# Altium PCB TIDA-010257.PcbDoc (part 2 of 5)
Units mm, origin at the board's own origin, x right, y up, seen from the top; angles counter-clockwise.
Board outline 250 x 270 mm, 2 copper layers (Top Layer, Bottom Layer), stack 1.575 mm thick; 458 components, 220 nets, 1154 pads, 1226 vias.
Unrouted connection lines stored in the file: 314.
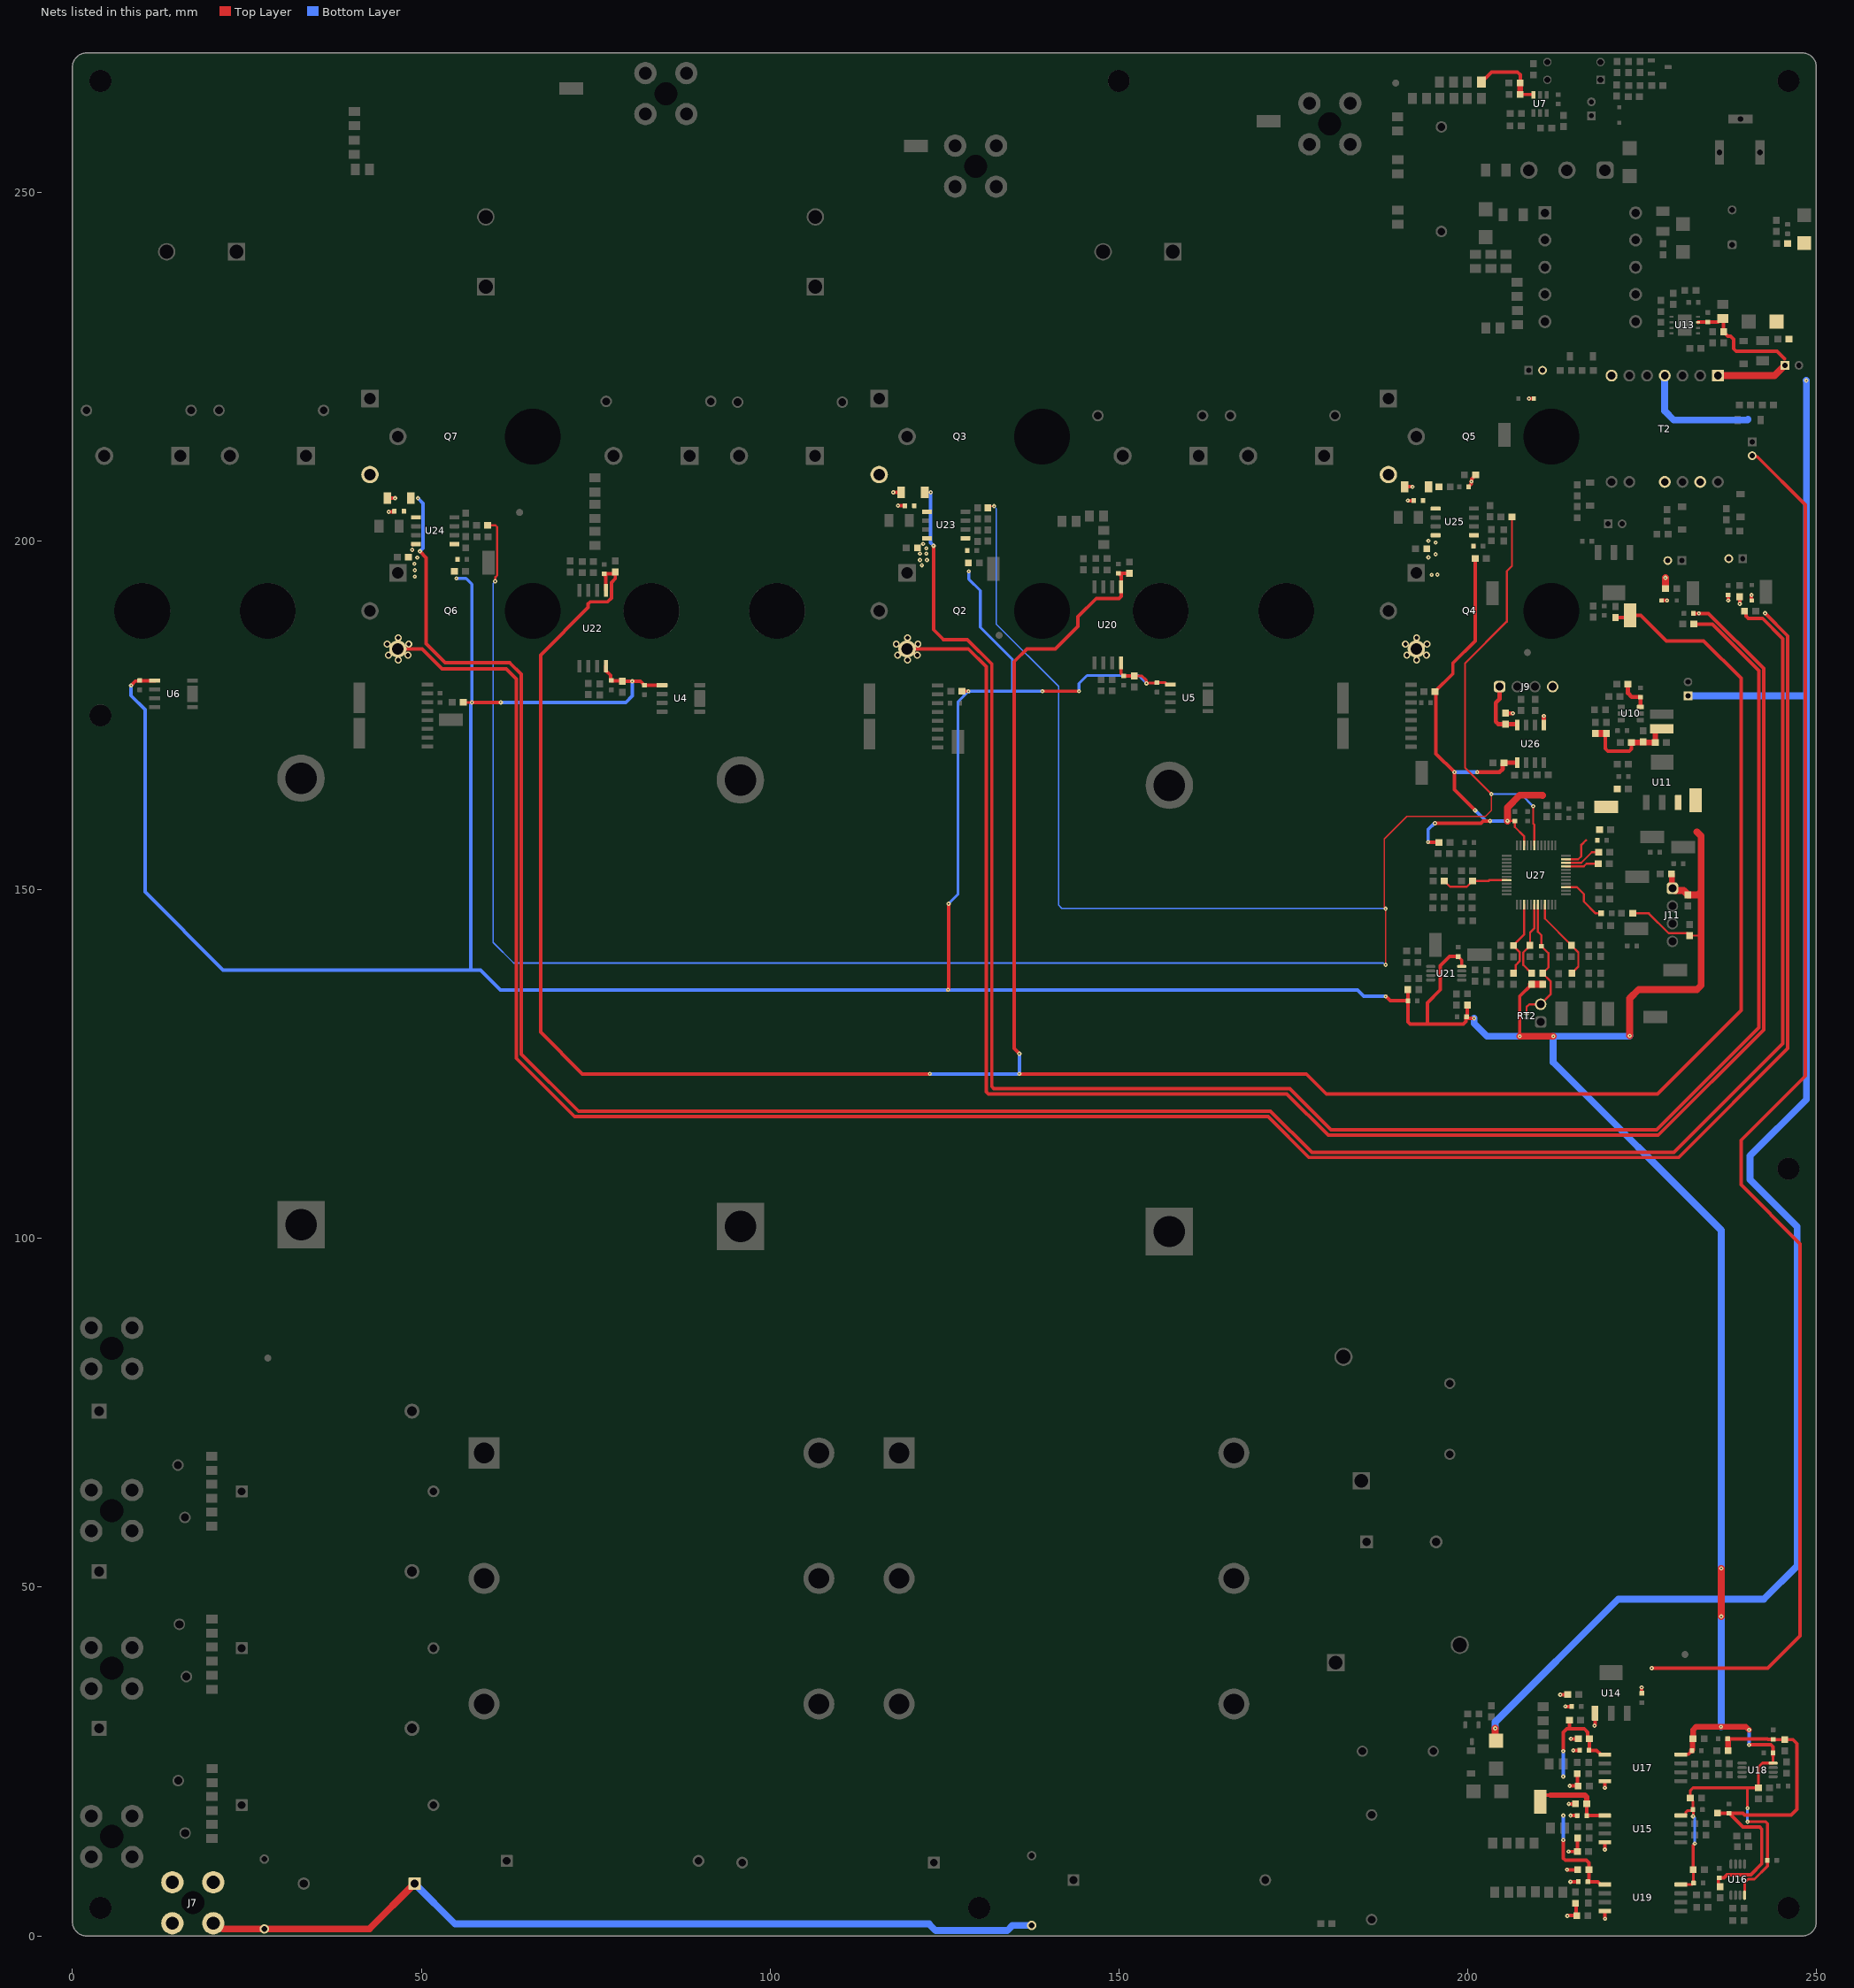
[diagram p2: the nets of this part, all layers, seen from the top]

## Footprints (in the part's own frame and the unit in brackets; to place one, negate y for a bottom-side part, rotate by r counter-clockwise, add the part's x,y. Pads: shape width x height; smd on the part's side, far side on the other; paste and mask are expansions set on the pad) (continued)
NGU0008C [mm] "SON, 8-Leads, Body 4x4mm, Pitch 0.8mm"
  rrect33% 0.6x0.3 smd: 1(-1.9,1.2) 2(-1.9,0.4) 3(-1.9,-0.4) 4(-1.9,-1.2) 5(1.9,-1.2) 6(1.9,-0.4) 7(1.9,0.4) 8(1.9,1.2)
  rrect8% 1.75x1.31 on Top Paste: 9(0,0.755) 9(0,-0.755)
  rrect5% 1.98x3 smd paste-1.5: 9(0,0)
  silkscreen extent -2.15,-2.15 2.15,2.15, body extent -2,-2 2,2, height 0.77
PT0048A-MFG [mm]
  rrect33% 1.4x0.3 smd paste-1000 mask+0: 1(-4.25,2.75) 2(-4.25,2.25) 3(-4.25,1.75) 4(-4.25,1.25) 5(-4.25,0.75) 6(-4.25,0.25) 7(-4.25,-0.25) 8(-4.25,-0.75) 9(-4.25,-1.25) 10(-4.25,-1.75) 11(-4.25,-2.25) 12(-4.25,-2.75) 25(4.25,-2.75) 26(4.25,-2.25) 27(4.25,-1.75) 28(4.25,-1.25) 29(4.25,-0.75) 30(4.25,-0.25) 31(4.25,0.25) 32(4.25,0.75) 33(4.25,1.25) 34(4.25,1.75) 35(4.25,2.25) 36(4.25,2.75)
  rrect33% 0.3x1.4 smd paste-1000 mask+0: 13(-2.75,-4.25) 14(-2.25,-4.25) 15(-1.75,-4.25) 16(-1.25,-4.25) 17(-0.75,-4.25) 18(-0.25,-4.25) 19(0.25,-4.25) 20(0.75,-4.25) 21(1.25,-4.25) 22(1.75,-4.25) 23(2.25,-4.25) 24(2.75,-4.25) 37(2.75,4.25) 38(2.25,4.25) 39(1.75,4.25) 40(1.25,4.25) 41(0.75,4.25) 42(0.25,4.25) 43(-0.25,4.25) 44(-0.75,4.25) 45(-1.25,4.25) 46(-1.75,4.25) 47(-2.25,4.25) 48(-2.75,4.25)
  silkscreen extent -5.65,-3.6 3.6,3.6, body extent -5.05,-5.05 5.05,5.05, height 0.25
PW_500x700 [mm] "Nichicon"
  rect 1.25x1.25 hole 0.711: 1(-1,0)
  round 1.25 hole 0.711: 2(1,0)
  silkscreen extent -2.8,-2.8 2.8,2.8, body extent -2.73,-2.75 2.75,2.75, height 8.01
Relay_T9AS1D12 [mm] "TH, 4-Leads, Body 32.51x27.43mm"
  rect 2.5x2.5 hole 1.98: 1(-8.89,5.08)
  round 2.6 hole 2.06: 2(8.89,7.62)
  round 1.6 hole 1.09: 3(-5.08,-7.62) 4(5.08,-7.62)
  silkscreen extent -13.79,-14.73 14.15,17.79, body extent -13.26,-14.73 14.17,17.78, height 20.45
SMA [mm] "Molded Diode, 2-Leads, Body 4.3x2.6mm, IPC Medium Density, based on OnSemi component dimensions and land pattern"
  rect 2x2 smd: 1(-2,0) 2(2,0)
  silkscreen extent -3.66,-1.57 2.79,1.57, body extent -2.6,-1.3 2.6,1.3, height 2.42
SOD-123 [mm] "On Semi recommended land pattern"
  rect 0.915x1.22 smd: 1(-1.637,0) 2(1.637,0)
  silkscreen extent -2.74,-1.17 2.03,1.17, body extent -1.93,-0.9 1.93,0.9, height 1.35
SOD-123FL [mm] "Copied from SOD-123"
  rect 0.915x1.22 smd: 1(-1.637,0) 2(1.637,0)
  silkscreen extent -2.74,-1.16 1.68,1.16, body extent -1.9,-0.9 1.9,0.9, height 1
SOD-323 [mm] "NXP recommended land pattern"
  rect 0.6x0.6 smd paste-0.05: 1(-1.1,0) 2(1.1,0)
  silkscreen extent -2.06,-0.86 1.53,0.86, body extent -1.3,-0.67 1.3,0.68, height 1.1
SOT-23 [mm] "SOT23, 3-Leads, Body 2.9x1.3mm, Pitch 0.95mm, Lead Span 2.5mm, IPC Medium Density"
  rrect50% 1x0.6 smd: 1(-1.2,0.95) 2(-1.2,-0.95) 3(1.2,0)
  silkscreen extent -1.63,-1.5 0.7,1.5, body extent -1.16,-1.45 1.21,1.45, height 1
Testpoint_Keystone_Miniature [mil] "Miniature SMT test point"
  rect 135x70 smd: 1(0,0)
  silkscreen extent -78,-46 78,45, body extent -52,-20 52,20, height 61
TI_Stacked_Overlay_Small [mm]
  silkscreen extent -10.63,-2.49 10.63,2.49
TO-3P [mm] "IXYS"
  rrect50% 2.5x2.5 hole 1.65: 1(-5.45,0)
  round 2.5 hole 1.65: 2(0,0) 3(5.45,0)
  body extent -7.8,-3.05 7.8,1.66, height 23.4
WCAP-FTBE_L18W8.5H15 [mm] "THT Film Capacitors, body 18x8.5mm"
  round 1.65 hole 1.1: 1(-7.5,0) 2(7.5,0)
  silkscreen extent -9.75,-4.75 9.75,4.75, body extent -9,-4.25 9,4.25, height 15.05
WCAP-FTXX_P15PL20_1800x600 [mm] "TH, 2-Leads, Body 18x6mm"
  round 1.65 hole 1.1: 1(-7.5,0) 2(7.5,0)
  silkscreen extent -9.25,-3.25 9.25,3.25, body extent -9.25,-3.25 9.25,3.25, height 12.5
WE-MAIA_3015 [mm] "SMD, 2-Leads, Body 3x3mm"
  rect 1.3x3.4 smd: 1(-1.05,0) 2(1.05,0)
  silkscreen extent -0.1,-1.6 0.1,1.6, body extent -1.6,-1.6 1.6,1.6, height 1.5
WEEE_Minimum [mm] "WEEElie bin"
  silkscreen extent -2.42,-4.38 2.52,2.65
WURTH_61300211121 [mm] "Header, 2.54mm, 2x1, TH"
  rrect50% 1.65x1.65 hole 1.15: 1(-1.27,0)
  round 1.65 hole 1.15: 2(1.27,0)
  body extent -2.54,-1.27 2.54,1.27, height 8.54
WURTH_61300411121 [mm] "Header, 2.54mm, 4x1, TH"
  rrect50% 1.65x1.65 hole 1.15: 1(-3.81,0)
  round 1.65 hole 1.15: 2(-1.27,0) 3(1.27,0) 4(3.81,0)
  body extent -5.08,-1.27 5.08,1.27, height 8.54
Wurth_694106301002 [mm] "WR-DC DC Power Jack, R/A, TH"
  rect 3.5x1.3 hole 0.8 slot 3 at 0 deg: 1(0,-2.9) 2(0,2.9)
  rect 1.3x3.5 hole 0.8 slot 3 at 90 deg: 3(-4.8,0.1)
  silkscreen extent -4.5,-3.8 4.9,10.7, body extent -4.9,-3.8 4.5,10.7, height 10.63
Wurth_WP-THRBU [mm] "Power Element Bush, M3, TH"
  round 3.2 hole 1.85: 1(-2.935,2.935) 1(-2.935,-2.935) 1(2.935,2.935) 1(2.935,-2.935)
  round 3.1 on Top Paste: ""(-2.935,2.935) ""(-2.935,-2.935) ""(2.935,2.935) ""(2.935,-2.935)
  round 3 hole 3.3 unplated mask+0.102: ""(0,0)
  silkscreen extent -3.5,-3.5 3.5,3.5, body extent -3.5,-3.5 3.5,3.5, height 3
ZLG_1000x2000 [mm] "TH, 2-Leads, Dia 10mm,  Lead Spacing 5mm"
  rrect50% 1.275x1.275 hole 0.85: 1(-2.5,0)
  round 1.275 hole 0.85: 2(2.5,0)
  silkscreen extent -5.25,-5.25 5.25,5.25, body extent -5.25,-5.25 5.26,5.25, height 22.01

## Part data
C1 C2 C3 C4 C5 C6: library part CMP-0090546-1, "1.2µF Film Capacitor 310V  Polypropylene (PP), Metallized Radial", Digikey Part Number=732-5766-ND, Manufacturer="Wurth Electronics", Mouser Part Number=710-890334027012CS, Operating Temperature Range="-40°C to +105°C", Tolerance_%=10%, ValueDisplayed=1.2uF
C7 C8: library part CMP-0009601-1, "CAP, CERM, 2200 pF, 250 V, +/- 20%, E, Cap, 7x12x9 mm", Cap_Case=CAPRD1000W60D900H1200, Manufacturer=MuRata, Supplier Part Number 1=490-7047-ND, TempCo=E, Tolerance_%=20%, Value1=Unknown, Value2=250V, ValueDisplayed=2200pF
C9 C54 C60 C61 C66 C70 C75: library part CMP-0074695-1, "CAP, AL, 47 µF, 35 V, +/- 20%, 0.38 ohm, TH", Cap_Case=5x11, Manufacturer=Chemi-Con, Supplier Part Number 1=565-4239-ND, Tolerance_%=20%, Value1="0.38 ohm", Value2=35V, ValueDisplayed=47µF
C10 C14 C18 C19 C22 C23 C27: library part CMP-0860742-1, "CAP, Film, 0.1 µF, 310 VAC/ VDC,+/- 10%, TH", Cap_Case=18x6x12mm, Manufacturer="Wurth Elektronik", Tolerance_%=10%, ValueDisplayed=0.1µF
C12 C17 C21 C28 C29 C30 C39 C45 C80 C85 C89 C95 C99 C104 C108 C112 C117 C121 C125 C128 C133 C136 C139 C140: library part CMP-0007432-5, "CAP, CERM, 1000 pF, 50 V, +/- 10%, X7R, 0603", Cap_Case=0603, Manufacturer=MuRata, Supplier Part Number 1=490-1494-1-ND, TempCo=X7R, Tolerance_%=10%, Value1=Unknown, Value2=50V, ValueDisplayed=1000pF
C13 C20 C26 C31 C32 C33 C36 C40 C46 C47 C50 C55 C56 C59 C62 C64 C68 C71 C76 C77 C79 C82 C84 C86 C88 C91 C93 C94 C96 C98 C101 C103 C105 C107 C110 C113 C114 C116 C119 C122 C124 C126 C130 C132 C134 C137 C143 C144 C145 C146 C148 C149 C152 C153 C157: library part CMP-0095617-1, "0603 50 V 0.1 uF X7R ±10% Tolerance SMT Multilayer Ceramic Capacitor", Digikey Part Number=490-8020-1-ND, Manufacturer=Murata, Mouser Part Number=81-GCM188R71H104KA7J, Operating Temperature Range="-55°C to +125°C", TempCo=15%, Temperature Characteristic=X7R, Tolerance_%=10%, ValueDisplayed=0.1uF
C15 C16 C24 C25: library part CMP-0010144-2, "CAP, AL, 470 uF, 450 V, +/- 20%, 0.42 ohm, TH", Cap_Case=35x50mm, Manufacturer=Vishay-Bccomponents, Supplier Part Number 1=4354PHBK-ND, Tolerance_%=20%, Value1="0.42 ohm", Value2=450V, ValueDisplayed=470uF
C34 C42 C44 C49 C57 C58 C63 C65 C67 C69 C73 C83 C92 C102 C111 C120 C150 C151: library part CMP-0007237-4, "CAP, CERM, 100 pF, 100 V, +/- 5%, C0G/NP0, 0603", Cap_Case=0603, Manufacturer=MuRata, Supplier Part Number 1=490-1351-1-ND, TempCo=C0G/NP0, Tolerance_%=5%, Value1=Unknown, Value2=100V, ValueDisplayed=100pF
C35: library part CMP-0078291-1, "CAP, AL, 470 µF, 35 V, +/- 20%, TH", Cap_Case=10x20mm, Manufacturer=Rubycon, Supplier Part Number 1=1189-2264-ND, Tolerance_%=20%, Value2=35V, ValueDisplayed=470µF
C37: library part CMP-0116358-1, "WCAP-FTBE Film Capacitor, THT, L18 x W8.5 x H15mm, 100nF, 1000V", Capacitance Tolerance=+/-10%, Insulation Resistance=9000MOhm, Manufacturer="Wurth Elektronik", Operating Temperature Max=85°C, Operating Temperature Min=-40°C, Rate of Voltage Rise=44V/us, Rated Voltage (DC)=1000V
C38: library part CMP-0008251-1, "CAP, CERM, 1000 pF, 250 V, +/- 10%, X7R, 0805", Cap_Case=0805, Manufacturer=MuRata, Supplier Part Number 1=490-3525-1-ND, TempCo=X7R, Tolerance_%=10%, Value1=Unknown, Value2=250V, ValueDisplayed=1000pF
C41: library part CMP-0010551-1, "CAP, AL, 10 uF, 35 V, +/- 20%, 0.95 ohm, TH", Cap_Case=5x7, Manufacturer=Nichicon, Supplier Part Number 1=493-1850-ND, Tolerance_%=20%, Value1="0.95 ohm", Value2=35V, ValueDisplayed=10uF
C43: library part CMP-0006834-5, "CAP, CERM, 470 pF, 50 V, +/- 10%, X7R, 0603", Cap_Case=0603, Manufacturer="Wurth Elektronik", Supplier Part Number 1=710-885012206081, TempCo=X7R, Tolerance_%=10%, Value1=Unknown, Value2=50V, ValueDisplayed=470pF
C48 C51 C52 C53 C74 C147 C154 C155: library part CMP-0007497-5, "CAP, CERM, 10 uF, 10 V, +/- 20%, X7R, 0603", Cap_Case=0603, Manufacturer=MuRata, Supplier Part Number 1=81-GRM188Z71A106MA3D, TempCo=X7R, Tolerance_%=20%, Value1=Unknown, Value2=10V, ValueDisplayed=10uF
C72: library part CMP-0084773-1, "CAP, CERM, 0.01 µF, 100 V,+/- 10%, X7R, AEC-Q200 Grade 1, 0603", Cap_Case=0603, Manufacturer=MuRata, TempCo=X7R, Tolerance_%=10%, Value2=100V, ValueDisplayed=0.01µF
C78 C81 C87 C90 C97 C100 C106 C109 C115 C118 C123 C129 C131 C141 C142: library part CMP-0079720-2, "CAP, CERM, 1 µF, 25 V,+/- 10%, X7R, 0603", Cap_Case=0603, Manufacturer=MuRata, Supplier Part Number 1=490-10888-1-ND, TempCo=X7R, Tolerance_%=10%, Value2=25V, ValueDisplayed=1µF
C127 C135 C138: library part CMP-0008954-2, "CAP, CERM, 10 uF, 50 V, +/- 10%, X5R, 1206", Cap_Case=1206, Manufacturer=MuRata, Supplier Part Number 1=490-5961-1-ND, TempCo=X5R, Tolerance_%=10%, Value1=Unknown, Value2=50V, ValueDisplayed=10uF
C156: library part CMP-0084284-1, "CAP, CERM, 2.2 µF, 10 V,+/- 10%, X7R, AEC-Q200 Grade 1, 0603", Cap_Case=0603, Manufacturer=MuRata, TempCo=X7R, Tolerance_%=10%, Value2=10V, ValueDisplayed=2.2µF
D1 D12: library part CMP-0078438-1, "Diode, Standard Recovery Rectifier, 1000 V, 1 A, SMA", Manufacturer="SMC Diode Solutions", Supplier Part Number 1=1655-1506-1-ND, Value1=1A, Value2=1.1V
D2: library part CMP-0028457-2, "Diode, Schottky, 30 V, 0.2 A, SOD-123", Manufacturer="ON Semiconductor", Value1=0.2A, Value2=0.8V
D3 D4: library part CMP-0078438-2, "Diode, Standard Recovery Rectifier, 1000 V, 1 A, SMA", Manufacturer="SMC Diode Solutions", Value1=1A, Value2=1.1V
D5 D6 D7 D8 D9 D10: library part CMP-0122869-4, "Diode 1200 V 30A Through Hole TO-247-2", Dc Blocking Voltage=1200V, Digikey Part Number=RHRG30120-ND, Forward Current=30A, Manufacturer=onsemi, Max Surge Forward Current=300A, Mouser Part Number=512-RHRG30120, Operating Temperature Range="-65°C to +175°C", Peak Reverse Current=250uA
D11 D13: library part CMP-0081099-1, "Diode, Schottky, 100 V, 2 A, SMA", Manufacturer="Diodes Inc.", Supplier Part Number 1=B2100A-13-FDICT-ND, Value1=2A, Value2=0.79V
D14 D17 D21 D23: library part CMP-0005835-4, "Diode, Zener, 18 V, 200 mW, SOD-323", Manufacturer="Diodes Inc.", Power_W=200mW, Value1=0.2W
D15 D16 D19 D20 D22 D24: library part CMP-0028625-2, "Diode, Schottky, 100 V, 1 A, SOD-123FL", Manufacturer="ON Semiconductor", Value1=1A, Value2=0.76V
D18: library part CMP-0084956-1, "Diode, TVS, Uni, 20 V, 32.4 Vc, 400 W, 12.3 A, SMA", Manufacturer=Littelfuse, Value1=32.4V
D25: library part CMP-0079922-3, "LED, Red, SMD", Color=Red, Manufacturer=Lite-On, Value1=W, Value2=2V
F1 F2 F3: library part CMP-0090478-2, Digikey Part Number=F10249-ND, Fuse Current=25A, Fuse Interrupt Dc Current=10000A, Manufacturer=Littelfuse, Mouser Part Number=576-0525025.MXEP, Operating Temperature Range="-55°C to +125°C"
FID1 FID2 FID3 FID4 FID5 FID6: library part CMP-0077181-1, "Fiducial mark.  There is nothing to buy or mount.", Manufacturer=N/A
GD1: library part CMP-0089811-1, "Gas Discharge Tube 3000V 5000A (5kA) ±20% 2 Pole Through Hole", Digikey Part Number=SA2-3000-CLT-STDCT-ND, Manufacturer=Bourns, Mouser Part Number=652-SA2-3000-CLTSTD, Operating Temperature Range="-40°C to +125°C"
J1 J2 J3 J4 J5 J6 J7 J8: library part CMP-0078526-1, "Power Element Bush, M3, TH", Current_A=50A, Manufacturer="Wurth Elektronik", Supplier Part Number 1=732-10882-1-ND
J9 J11: library part CMP-0054798-2, "Header, 2.54 mm, 4x1, Gold, TH", Color=Black, Manufacturer="Wurth Elektronik", Supplier Part Number 1=732-5317-ND
J10: library part CMP-0054778-3, "WR-DC DC Power Jack, R/A, TH", Color=Black, Manufacturer="Wurth Elektronik", Supplier Part Number 1=732-5930-ND
J12: library part CMP-0054794-2, "Header, 2.54 mm, 2x1, Gold, TH", Color=Black, Manufacturer="Wurth Elektronik", Supplier Part Number 1=732-5315-ND
K1 K2: library part CMP-0078608-2, "Relay, SPST-NO (1 Form A), 30 A, 15 V, TH", Coil Current_A=66.7mA, Coil Power_W=1W, Coil Resistance_ohm=225, Coil Voltage_VDC=15V, Contact Rating_A=30A, Manufacturer="TE Connectivity", Turn Off Voltage (Min)_VDC=1.5V, Turn On Voltage (Max)_VDC=11.25V
L1 L2: library part CMP-0122552-1, "3 PHASES COMMON MODE CHOKE", Manufacturer="YAXIN ELECTRONICS", Operating Temperature Range=to
L3 L6 L8 L10: library part CMP-0003201-2, "Ferrite Bead, 1000 ohm @ 100 MHz, 0.6 A, 0603", Manufacturer="Wurth Elektronik", Supplier Part Number 1=732-4670-1-ND, Value1="0.3 ohm", Value2=0.6A, ValueDisplayed="1000 ohm"
L4 L5 L7: library part CMP-0122551-1, "PFC INDUCTANCE 350uH 31A", Manufacturer="YAXIN ELECTRONICS", Operating Temperature Range=to, Test Frequency=100kHz, Tolerance_%=12%
L9: library part CMP-0064362-1, "Inductor, Shielded, Powdered Iron, 6.8 uH, 1.1 A, 0.287 ohm, AEC-Q200 Grade 1, SMD", Manufacturer="Wurth Elektronik", Supplier Part Number 1=732-6942-1-ND, Value1="0.287 ohm", Value2=1.1A, ValueDisplayed=6.8uH
Logo1: library part CMP-0074844-1
Logo2 Logo5: library part CMP-0074838-1, "Texas Instrument Corporate Signature"
Logo3: library part CMP-0074847-1, "FCC_disclaimer"
Logo4: library part CMP-0074769-1
LOGO6 LOGO8: library part CMP-0074837-1, "IEC 61010-1 Hot Surface Warning"
LOGO7 LOGO9: library part CMP-0074835-1, "IEC 61010-1 High Voltage Warning"
MP1 MP2 MP3 MP4 MP5 MP6 MP7 MP8: library part CMP-0087151-1, Manufacturer="Wurth Electronics"
Q1: library part CMP-0000777-1, "MOSFET, N-CH, 60 V, 0.32 A, AEC-Q101, SOT-23", Alternate Manufacturer=None, Manufacturer="ON Semiconductor", Supplier Part Number 1=2V7002KT1GOSCT-ND, Value1=2, Value2="0.7 nC"
Q2 Q3 Q4 Q5 Q6 Q7: library part CMP-0122917-3, "IGBT 650 V 80 A 305 W Through Hole PG-TO247-3", Collector Current=80A, Digikey Part Number=448-IKW50N65F5FKSA1-ND, Manufacturer=Infineon, Mouser Part Number=726-IKW50N65F5FKSA1, Operating Temperature Range="-40°C to +175°C", Power_W=305W
Q8: library part CMP-0082176-2, "MOSFET, N-CH, 1500 V, 4 A, TO-3P", Alternate Manufacturer=None, Manufacturer=Renesas, Supplier Part Number 1=2SK1835-E-ND, Value1="? ohm", Value2="? nC"
R1 R85 R98 R109 R119 R130 R135 R137 R138 R140 R142 R143 R146 R148: library part CMP-0022736-4, "RES, 100, 1%, 0.1 W, 0603", Manufacturer=Yageo, Power_W=100mW, Supplier Part Number 1=311-100HRCT-ND, TempCo="100 ppm/C", Tolerance_%=1%, Value2=0.1W, Value_Code=100R, ValueDisplayed=100
R2 R37 R43 R49 R84 R87 R94 R97 R100 R102 R108 R111 R118 R121 R129 R132 R151 R154 R155 R159 R160 R161: library part CMP-0022746-5, "RES, 10.0 k, 1%, 0.1 W, 0603", Manufacturer=Yageo, Power_W=100mW, Supplier Part Number 1=311-10.0KHRCT-ND, TempCo="100 ppm/C", Tolerance_%=1%, Value2=0.1W, Value_Code=10k0, ValueDisplayed=10.0k
R3 R4 R5 R6 R7 R8 R9 R10 R11 R14 R16 R17 R19 R20 R21 R27 R29 R30 R31 R32 R33 R35 R36 R41 R42 R68 R80 R81 R82 R91 R92 R93 R104 R105 R106 R114 R115 R116 R125 R126 R127: library part CMP-0021522-3, "RES, 1.00 M, 1%, 0.125 W, AEC-Q200 Grade 0, 0805", Manufacturer=Panasonic, Power_W=125mW, Supplier Part Number 1=P1.00MCCT-ND, TempCo="100 ppm/C", Tolerance_%=1%, Value2=0.125W, Value_Code=1M00, ValueDisplayed=1.00M
R12 R25 R51 R53 R58 R61 R64 R67 R75: library part CMP-0025885-5, "RES, 0, 5%, 0.1 W, 0603", Manufacturer=Yageo, Power_W=100mW, Supplier Part Number 1=311-0.0GRCT-ND, TempCo="200 ppm/C", Tolerance_%=5%, Value2=0.1W, Value_Code=0000, ValueDisplayed=0
R13 R15 R18 R22 R23 R24 R47 R59 R60 R65 R69 R71 R78 R144 R145 R147 R149 R150 R156 R157 R158: library part CMP-0022895-5, "RES, 1.00 k, 1%, 0.1 W, 0603", Manufacturer=Yageo, Power_W=100mW, Supplier Part Number 1=311-1.00KHRCT-ND, TempCo="100 ppm/C", Tolerance_%=1%, Value2=0.1W, Value_Code=1k00, ValueDisplayed=1.00k
R26 R34 R63: library part CMP-0018320-2, "RES, 47.0, 1%, 0.25 W, 1206", Manufacturer="Yageo America", Power_W=250mW, Supplier Part Number 1=311-47.0FRCT-ND, TempCo="100 ppm/C", Tolerance_%=1%, Value2=0.25W, Value_Code=47R0, ValueDisplayed=47.0
R28 R45 R50 R62 R66 R70: library part CMP-0023142-5, "RES, 49.9 k, 1%, 0.1 W, 0603", Manufacturer=Yageo, Power_W=100mW, Supplier Part Number 1=311-49.9KHRCT-ND, TempCo="100 ppm/C", Tolerance_%=1%, Value2=0.1W, Value_Code=49k9, ValueDisplayed=49.9k
R40 R95: library part CMP-0022751-4, "RES, 10.0, 1%, 0.1 W, 0603", Manufacturer=Yageo, Power_W=100mW, Supplier Part Number 1=311-10.0HRCT-ND, TempCo="100 ppm/C", Tolerance_%=1%, Value2=0.1W, Value_Code=10R0, ValueDisplayed=10.0
R44 R152 R153: library part CMP-0022991-5, "RES, 2.40 k, 1%, 0.1 W, 0603", Manufacturer=Yageo, Power_W=100mW, Supplier Part Number 1=311-2.40KHRCT-ND, TempCo="100 ppm/C", Tolerance_%=1%, Value2=0.1W, Value_Code=2k40, ValueDisplayed=2.40k
R46 R54 R55 R122 R133: library part CMP-0022735-5, "RES, 100 k, 1%, 0.1 W, 0603", Manufacturer=Yageo, Power_W=100mW, Supplier Part Number 1=311-100KHRCT-ND, TempCo="100 ppm/C", Tolerance_%=1%, Value2=0.1W, Value_Code=100k
R48 R136 R139 R141: library part CMP-0018676-1, "RES, 3.0, 5%, 0.25 W, 1206", Manufacturer=Vishay-Dale, Power_W=250mW, Supplier Part Number 1=541-3.0ECT-ND, TempCo="200 ppm/C", Tolerance_%=5%, Value2=0.25W, Value_Code=3R00, ValueDisplayed=3.0
R52: library part CMP-0022899-4, "RES, 1.00 M, 1%, 0.1 W, 0603", Manufacturer=Yageo, Power_W=100mW, Supplier Part Number 1=311-1.00MHRCT-ND, TempCo="100 ppm/C", Tolerance_%=1%, Value2=0.1W, Value_Code=1M00, ValueDisplayed=1.00M
R56 R77 R79 R88 R90 R101 R103 R112: library part CMP-0022777-5, "RES, 12.4 k, 1%, 0.1 W, 0603", Manufacturer=Yageo, Power_W=100mW, Supplier Part Number 1=311-12.4KHRCT-ND, TempCo="100 ppm/C", Tolerance_%=1%, Value2=0.1W, Value_Code=12k4, ValueDisplayed=12.4k
R72 R73 R76: library part CMP-0022808-4, "RES, 150 k, 1%, 0.1 W, 0603", Manufacturer=Yageo, Power_W=100mW, Supplier Part Number 1=311-150KHRCT-ND, TempCo="100 ppm/C", Tolerance_%=1%, Value2=0.1W, Value_Code=150k
R83 R86 R96 R99 R107 R110 R117 R120 R128 R131: library part CMP-0022945-5, "RES, 24.0 k, 1%, 0.1 W, 0603", Manufacturer=Yageo, Power_W=100mW, Supplier Part Number 1=311-24.0KHRCT-ND, TempCo="100 ppm/C", Tolerance_%=1%, Value2=0.1W, Value_Code=24k0, ValueDisplayed=24.0k
R89: library part CMP-0023198-5, "RES, 5.10 k, 1%, 0.1 W, 0603", Manufacturer=Yageo, Power_W=100mW, Supplier Part Number 1=311-5.10KHRCT-ND, TempCo="100 ppm/C", Tolerance_%=1%, Value2=0.1W, Value_Code=5k10, ValueDisplayed=5.10k
R113 R124: library part CMP-0022852-5, "RES, 18.0 k, 1%, 0.1 W, 0603", Manufacturer=Yageo, Power_W=100mW, Supplier Part Number 1=311-18.0KHRCT-ND, TempCo="100 ppm/C", Tolerance_%=1%, Value2=0.1W, Value_Code=18k0, ValueDisplayed=18.0k
R123 R134: library part CMP-0022925-5, "RES, 22.0 k, 1%, 0.1 W, 0603", Manufacturer=Yageo, Power_W=100mW, Supplier Part Number 1=311-22.0KHRCT-ND, TempCo="100 ppm/C", Tolerance_%=1%, Value2=0.1W, Value_Code=22k0, ValueDisplayed=22.0k
RT1: library part CMP-0123150-1, "Ceramic PTC Thermistor", Manufacturer="Thinking Electronic", Operating Temperature Range="-20°C to +85°C", Tolerance_%=30%
RT2: library part CMP-0084566-1, "Thermistor, DEC0002A (X1SON-2)", Alternate Manufacturer="Texas Instruments", Alternate PartNumber=TMP6131DECT
RV1 RV2 RV3: library part CMP-0065393-2, "VARISTOR 560V 4.5KA, TH", Manufacturer=Bourns, Supplier Part Number 1=MOV-14D561KTRCT-ND
T1: library part CMP-0122470-1, "TRANSFORMER", Frequency_Fixed=100kHz, Manufacturer="Wurth Electornics", Operating Temperature Range="-40°C to +125°C", Voltage_Isolation_Vrms=3.2kV
T2: library part CMP-0123200-1, "TRANSFORMER", Frequency_Fixed=180kHz, Manufacturer="Wurth Electornics", Operating Temperature Range="-40°C to +125°C"
TP1 TP2 TP3 TP4 TP5 TP6 TP7 TP8 TP9 TP10 TP11 TP12 TP13 TP14 TP15 TP16 TP17 TP18 TP19 TP20 TP21 TP22 TP23 TP24 TP25 TP26 TP27: library part CMP-0055152-2, "Test Point, Miniature, SMT", Manufacturer="Keystone Electronics", Supplier Part Number 1=36-5015TR-ND
U1 U2 U3: library part CMP-0121162-1, "Precision 250kHz Hall-Effect Current Sensor With ±1.3kV Reinforced Isolation Working Voltage, Overcurrent Detection and Ambient Field Rejection", Coil Resistance=0.7mΩ, Current Sensitivity=50mV/A, Digikey Part Number=296-TMCS1123B2AQDVGRCT-ND, Manufacturer="Texas Instruments", Max Sensing Current=65A, Max Supply Voltage=5.5V, Min Supply Voltage=3V, Operating Supply Current=11mA, Operating Temperature Range="-40°C to +125°C"
U4 U5 U6: library part CMP-0122473-1, "Automotive ±1.5°C, 3-kVRMS Isolated Temperature Sensor With Analog Output With < 2 Seconds Response Time and 500VRMS Working Voltage", Manufacturer="Texas Instruments", Max Supply Voltage=5.5V, Min Supply Voltage=2.3V, Operating Supply Current=10uA, Operating Temperature Range="-40°C to +150°C"
U7: library part CMP-0121336-1, "Current-Mode Flyback Controller with Secondary-Side Regulation (SSR) for Off-Line Applications", Manufacturer="Texas Instruments", Max Supply Voltage=26V, Min Supply Voltage=10V, Nominal Supply Current=1.8mA, Operating Temperature Range="-40°C to +125°C", Switching Frequency=65kHz
U8: library part CMP-0006159-2, "Optocoupler, 5 kV, 50% min CTR, TH", Manufacturer="Sharp Microelectronics", Supplier Part Number 1=425-2766-ND, Voltage_Isolation_Vrms=5kV
U9: library part CMP-0032994-1, "Adjustable Precision Shunt Regulator, 34 ppm / degC, 100 mA, -40 to 125 degC, 3-pin SOT-23 (DBZ), Green (RoHS & no Sb/Br)", Manufacturer="Texas Instruments", Rating=Catalog, Temp Coeff(Max)(ppm/ degree C)=92, Temp Coeff(Typ)(ppm/ degree C)=34
U10: library part CMP-0073969-3, "4.5V to 28V Input, 2A Output, EMI Friendly Synchronous Step-Down Converter, DDC0006A (SOT-23-THIN-6)", Alternate Manufacturer="Texas Instruments", Alternate PartNumber=TPS54202DDCT, Operating Temperature Range="-40 to 125 C", Rating=Catalog
U11 U12 U14: library part CMP-0122558-1, "1-A 16-V high-PSRR linear voltage regulator 4-SOT-223 -40 to 125", Digikey Part Number=296-TLV76133DCYRCT-ND, Dropout Voltage=0.9V, Manufacturer="Texas Instruments", Max Supply Voltage=16V, Min Supply Voltage=4.8V, Mouser Part Number=595-TLV76133DCYR, Nominal Supply Current=65uA, Operating Temperature Range="-40°C to +125°C", Output Voltage=3.3V
U13: library part CMP-0750185-1, "LM25180 42-VIN PSR Flyback DC/DC Converter With 65-V, 1.5-A Integrated Power MOSFET, NGU0008C (WSON-8)", Alternate Manufacturer="Texas Instruments", Alternate PartNumber=LM25180NGUT
U15 U17 U19 U20 U22: library part CMP-0092814-1, "Precision, ±5-V Input, Reinforced Isolated Amplifier", Input Bias Current=0.0035uA, Input Offset Voltage=0.4mV, Manufacturer="Texas Instruments", Max Supply Voltage=5.5V, Min Supply Voltage=3V, Operating Temperature Range="-40°C to +125°C", Output Current Per Channel=14mA
U16 U18 U21: library part CMP-0084063-1, "10-MHz, Low-Noise, RRIO, CMOS Operational Amplifier for Cost-Sensitive Systems, DGK0008A (VSSOP-8)", Alternate Manufacturer="Texas Instruments", Alternate PartNumber=TLV9062IDGKT, Operating Temperature Range="-40 to 125 C", Rating=Catalog
U23 U24 U25: library part CMP-0065064-4, "4.3-A, 3-kVRMS Isolated Single-Channel Gate Drivers, D0008B (SOIC-8)", Alternate Manufacturer="Texas Instruments", Alternate PartNumber=UCC5350MCD
U26: library part CMP-0089949-1, "Low Speed, General Purpose, Robust EMC, Dual-Channel Digital Isolators", Manufacturer="Texas Instruments", Max Supply Voltage=5.5V, Min Supply Voltage=1.71V, Operating Temperature Range="to +150°C"
U27: library part CMP-0096487-1, "Real-Time Microcontrollers", Frequency_Fixed=120MHz, Manufacturer="Texas Instruments", Max Supply Voltage=3.63V, Min Supply Voltage=2.8V, Operating Temperature Range="-40°C to +125°C"

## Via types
v1: diameter 1, hole 0.6, Top Layer to Bottom Layer, 760 vias
v2: diameter 0.6, hole 0.2, Top Layer to Bottom Layer, 452 vias
v3: diameter 1.27, hole 0.711, Top Layer to Bottom Layer, 10 vias
v4: diameter 0.5, hole 0.2, Top Layer to Bottom Layer, 4 vias

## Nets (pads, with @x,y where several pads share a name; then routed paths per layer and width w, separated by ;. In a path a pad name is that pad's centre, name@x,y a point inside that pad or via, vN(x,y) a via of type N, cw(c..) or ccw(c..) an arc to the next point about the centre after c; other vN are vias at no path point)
1.65V: C86.2 C93.2 C96.2 C105.2 R88.1 R95.2 R101.1 R112.1 | length 51.3
  Top Layer w0.5: R88.1@235.831,17.613 235.851,17.593 C86.2@237.489,17.593 ; C105.2@235.957,8.166 235.957,7.296 R112.1@236.182,7.071 ; C105.2@236.076,8.334 236.084,8.342 236.753,8.342 237.187,8.776 240.603,8.776 242.173,10.346 242.173,15.322 241.875,15.619 239.488,15.619 C86.2@237.534,17.573 ; C96.2@237.324,28.265 242.994,28.265 243.066,28.193 C93.2@243.816,28.193 ; C86.2@237.509,17.573 C86.2@237.534,17.573 ; 244.192,28.145 R95.2@245.5,28.145 246.646,28.145 247.218,27.573 247.218,18.167 246.397,17.346 239.712,17.346 239.485,17.573 C86.2@237.534,17.573
  Top Layer w0.8: C96.2@237.324,28.233 237.357,28.2 R101.1@237.357,26.566
3.3V: C31.2 C32.2 C33.2 C81.2 C82.1 C84.2 C90.2 C91.1 C100.2 C101.1 C103.2 C109.2 C110.1 C113.2 C114.1 C118.2 C119.1 C122.2 C123.1 C124.2 C129.1 C130.2 C131.1 C132.2 C141.2 C152.2 C153.2 C155.2 J11.1 L3.1 L6.1 L8.1 L10.1 R53.1 R94.2 R122.2 R133.2 R150.2 R152.2 R153.2 R154.1 R156.1 R157.2 TP8.1 U4.1 U5.1 U6.1 U15.8 U16.8 U17.8 U18.8 U19.8 U20.8 U21.8 U22.8 U23.1 U24.1 U25.1 U26.1 U27.35 U27.46 | length 809
  Top Layer w0.3: v2(205.724,159.877) C153.2@206.78,159.877 206.78,159.015 208.088,157.707 U27.46@208.088,156.377 ; U27.35@214.088,154.377 215.86,154.377 216.31,154.827 216.31,156.455 216.982,157.127 ; R156.1@223.672,146.628 225.982,146.628 228.815,143.795 231.501,143.795 231.826,143.47 R153.2@231.826,143.445 233.44,143.445
  Top Layer w0.4: L8.1@56.036,176.905 56.056,176.885 57.23,176.885 v2(57.25,176.865) ; L3.1@127.531,178.476 v2(128.45,178.476) ; v2@128.427,195.635 128.457,195.665 v2(128.502,195.665) ; v2(139.05,178.479) v2(144.299,178.479) ; U20.8@150.328,182.55 150.328,181.006 150.665,180.67 C110.1@150.69,180.67 ; C109.2@152.245,180.675 C109.2@152.25,180.68 153.306,180.68 153.937,180.048 153.937,179.637 v2(153.968,179.606) 154.007,179.644 155.426,179.644 C32.2@155.486,179.705 155.636,179.705 156.655,179.705 156.925,179.435 U5.1@157.4,179.435 ; C114.1@198.648,140.431 198.673,140.431 199.165,139.938 U21.8@199.165,139.019 ; U19.8@230.577,7.375 C101.1@232.234,7.375 ; U15.8@230.577,17.251 231.177,17.251 231.277,17.351 231.277,17.711 231.511,17.946 232.363,17.946 232.363,17.244 232.325,17.205 v2(232.325,17.151) ; C82.1@232.325,18.096 232.325,19.278 232.245,19.358 232.245,19.512 231.97,19.787 C81.2@231.945,19.787 231.945,20.867 232.302,21.225 240.134,21.225 ; C101.1@232.401,7.567 232.371,7.597 232.371,9.439 C100.2@232.341,9.469 232.341,13.015 v2(232.577,13.251) ; 233.44,143.445 233.482,143.487 ; U16.8@239.712,5.842 239.712,7.619 240.219,8.126 241.124,8.126 242.994,9.997 242.994,16.123 242.76,16.357 240.146,16.357 v2(240.134,16.369) ; v2(240.134,18.321) 240.134,21.225 ; 243.801,25.821 243.801,24.778 U18.8@243.807,24.772 242.272,24.772 241.692,24.192 R94.2@241.692,21.225 240.134,21.225
  Top Layer w0.5: v2(8.391,179.3) 9.034,179.943 9.571,179.943 C33.2@9.646,180.018 ; C33.2@9.646,179.998 U6.1@11.784,179.998 ; v2@57.255,176.905 57.271,176.889 61.385,176.889 v2(61.401,176.873) ; U22.8@76.47,182.05 76.47,181.45 77.15,180.77 77.15,180.096 77.283,179.963 78.757,179.963 C118.2@78.815,179.905 v2(80.25,179.905) 81.429,179.905 81.9,179.434 81.9,179.409 81.975,179.334 C31.2@82,179.334 82.006,179.34 84.519,179.34 U4.1@84.525,179.346 ; v2(125.5,135.651) 125.5,135.678 125.599,135.777 v2(125.599,148.001) ; C110.1@150.69,180.67 150.695,180.675 C109.2@152.245,180.675 ; v2(188.259,134.729) 188.282,134.729 188.91,134.101 C113.2@191.45,134.101 ; R122.2@191.444,135.694 191.447,135.692 191.447,134.103 C113.2@191.45,134.101 ; v2(194.345,156.837) 194.37,156.812 R154.1@195.879,156.812 ; v2(195.324,159.546) 201.938,159.546 202.25,159.858 203.219,159.858 v2(203.238,159.877) ; C114.1@198.648,140.431 197.418,140.431 196.09,139.103 196.09,135.669 194.222,133.801 194.222,130.742 ; R133.2@199.979,133.489 199.979,131.948 199.855,131.825 C122.2@199.855,131.8 199.78,131.725 199.78,131.125 199.398,130.742 194.222,130.742 ; C122.2@200.067,131.589 200.923,131.589 v2(200.942,131.57) ; C132.2@200.893,199.321 C132.2@200.864,199.292 C132.2@200.939,199.217 ; U25.1@200.893,200.828 U25.1@200.922,200.857 ; C131.1@200.939,197.679 C131.1@201.076,197.542 201.076,185.669 197.895,182.488 197.895,180.985 195.349,178.44 L6.1@195.324,178.44 195.478,178.286 195.478,169.524 v2(198.115,166.887) 198.115,164.378 v2(201.092,161.402) ; v2(207.477,129) 207.477,134.729 209.163,136.415 L10.1@209.163,136.44 ; U17.8@230.577,26.002 230.627,26.052 231.679,26.052 232.168,26.541 C91.1@232.168,26.566 ; C90.2@232.243,28.183 C90.2@232.325,28.265 ; v2(240.359,27.395) 243.508,27.395 243.801,27.102 243.801,25.821 ; C113.2@191.45,134.101 191.45,131.077 191.784,130.742 194.222,130.742
  Top Layer w0.6: v2(201.401,166.887) 204.578,166.887 205.037,167.346 205.037,168.062 205.212,168.237 C141.2@205.237,168.237 U26.1@207.127,168.237
  Top Layer w0.8: R157.2@229.239,152.297 229.302,152.234 229.302,150.289 J11.1@229.364,150.226 ; C91.1@232.168,26.566 232.243,26.641 C90.2@232.243,28.183 ; C90.2@232.325,28.265 232.325,29.553 232.751,29.98 v2(236.33,29.98) 239.909,29.98 v2(240.359,29.53)
  Top Layer w1: v2(205.724,159.877) 205.724,161.807 207.489,163.571 210.699,163.571 210.727,163.543 ; v2(207.477,129) v2(212.284,129) ; L10.1@209.163,136.44 R150.2@210.779,136.44 ; v2(223.25,129.081) 223.25,134.418 224.548,135.716 232.897,135.716 233.482,136.302 233.482,143.487 233.482,149.712 ; J11.1@229.364,150.226 229.689,149.901 230.986,149.901 R152.2@231.601,149.286 233.057,149.286 233.482,149.712 ; 232.874,158.316 233.482,157.707 233.482,149.712 ; v2(236.368,45.8) v2(236.368,52.7)
  Bottom Layer w0.4: v2(55.049,194.658) 56.414,194.658 57.255,193.816 v2@57.255,176.905 ; v2(125.599,148.001) 126.952,149.353 126.952,176.977 v2(128.45,178.476) ; v2(128.502,195.665) 128.502,194.552 130.145,192.909 130.145,187.648 134.75,183.043 134.75,178.714 134.516,178.479 ; v2@128.573,178.353 128.7,178.479 134.516,178.479 ; v2(139.05,178.479) 134.516,178.479 ; v2(144.299,178.479) 144.299,179.594 145.448,180.743 152.819,180.743 v2@153.968,179.594 ; v2(232.325,17.151) 232.325,17.097 232.577,16.845 v2(232.577,13.251) ; v2(240.134,16.369) v2(240.134,18.321)
  Bottom Layer w0.5: v2(8.391,179.3) 8.391,177.848 10.396,175.843 10.396,149.704 21.6,138.5 57.102,138.5 ; v2(57.25,176.865) 57.25,176.838 57.102,176.69 57.102,138.5 ; v2(61.401,176.873) 61.412,176.885 79.334,176.885 80.25,177.801 v2(80.25,179.905) ; v2(188.259,134.729) 185.121,134.729 184.2,135.651 v2(125.5,135.651) 61.349,135.651 58.5,138.5 57.102,138.5 ; v2(194.345,156.837) 194.345,158.642 195.249,159.546 v2(195.324,159.546) ; v2(201.092,161.402) 202.598,159.896 203.219,159.896 v2(203.238,159.877) v2(205.724,159.877) ; v2(240.359,27.395) v2(240.359,29.53)
  Bottom Layer w0.6: v2(198.115,166.887) v2(201.401,166.887)
  Bottom Layer w1: v2(200.942,131.57) 200.942,130.849 202.791,129 v2(207.477,129) ; v2(223.25,129.081) 223.169,129 v2(212.284,129) 212.284,125.269 236.368,101.185 v2(236.368,52.7) ; v2(236.33,29.98) 236.368,30.018 v2(236.368,45.8)
3.3V_ACSensing: C78.1 C79.2 C87.1 C88.2 C97.1 C98.2 R75.1 TP13.1 U15.1 U17.1 U19.1 | length 44.8
  Top Layer w0.5: TP13.1@210.396,19.243 210.396,19.547 211.035,20.186 211.879,20.186 ; v2@213.713,17.26 v2(213.722,17.251) ; v2(213.713,26.479) 213.713,29.184 214.213,29.684 214.577,29.684 ; v2(213.722,13.751) 213.722,11.125 214.015,10.832 217.04,10.832 217.387,10.485 C97.1@217.387,9.469 217.387,7.926 217.24,7.779 C98.2@217.24,7.754 218.698,7.754 219.077,7.375 U19.1@219.677,7.375 ; R75.1@214.611,30.926 214.611,29.718 214.577,29.684 ; C78.1@217.075,18.923 C79.2@217.075,17.251 U15.1@219.677,17.251 ; U17.1@219.677,26.002 219.077,26.002 219.027,26.052 219.027,26.062 218.486,26.603 C88.2@217.411,26.603 217.441,26.634 217.441,28.26 217.447,28.265 217.222,28.49 217.222,29.198 216.736,29.684 214.577,29.684
  Top Layer w0.8: 211.879,20.186 216.782,20.186 217.075,19.893 C78.1@217.075,18.923
  Bottom Layer w0.5: v2(213.713,22.843) v2(213.713,26.479) ; v2(213.722,13.751) v2(213.722,17.251)
3.3V_DCSensing: C106.1 C107.2 C115.1 C116.2 R58.1 TP9.1 U20.1 U22.1 | length 410.5
  Top Layer w0.5: C116.2@76.15,195.225 76.15,195.25 76.225,195.325 C116.2@76.25,195.325 C116.2@76.275,195.325 ; U22.1@76.47,192.95 76.47,195.08 76.35,195.2 76.35,195.25 C116.2@76.275,195.325 ; C115.1@77.59,195.325 C116.2@76.275,195.325 ; C115.1@77.815,195.566 77.815,194.61 77.265,194.06 77.265,191.85 76.714,191.3 74.223,191.3 73.93,191.007 73.93,190.501 67.1,183.671 67.1,129.6 73.1,123.6 v2(122.9,123.6) ; v2(135.75,123.6) 176.9,123.6 179.75,120.75 227.24,120.75 239.2,132.71 239.2,180.331 233.84,185.692 228.515,185.692 224.847,189.36 TP9.1@223.3,189.36 222.987,189.047 R58.1@221.209,189.047 ; v2(135.75,126.5) 135,127.25 135,182.731 136.819,184.55 140.902,184.55 144.15,187.798 144.15,189.179 146.771,191.8 150.035,191.8 150.328,192.093 U20.1@150.328,193.45 150.328,195.018 149.978,195.368 C107.2@149.953,195.368 ; C107.2@149.978,195.391 151.477,195.391 C106.1@151.5,195.414
  Bottom Layer w0.5: v2(122.9,123.6) v2(135.75,123.6) v2(135.75,126.5)
5.4V: C49.2 C51.1 C52.1 L9.2 R51.2 R54.2 TP7.1 U11.3 | length 14.7
  Top Layer w0.5: C49.2@219.738,172.25 219.738,170.259 220.097,169.9 223.208,169.9 223.501,170.193 C52.1@223.501,171.129
  Top Layer w0.8: C52.1@223.501,171.129 R51.2@226.915,171.129 226.915,172.848 227.165,173.098 L9.2@227.829,173.098
  Top Layer w1: R54.2@218.346,172.431 R54.2@218.341,172.426 C49.2@219.903,172.426
5V_ISO: C142.1 J9.1 U26.8 | length 8.6
  Top Layer w0.6: J9.1@204.578,179.131 204.578,177.332 204.055,176.808 204.055,174.111 204.406,173.759 C142.1@205.458,173.759 207.127,173.759 U26.8@207.127,173.637
15V: C9.1 C47.2 C61.1 C62.2 C63.1 C67.2 D1.1 D3.2 D18.2 R25.1 R52.2 R68.2 T2.1 U10.3 U13.3 | length 280.3
  Top Layer w0.5: U13.3@233.04,231.383 233.069,231.412 234.424,231.412 C62.2@234.453,231.442 235.961,231.442 236.436,231.917 R68.2@236.601,231.917 236.71,231.808 C67.2@236.71,230.021 236.71,229.996 237.335,229.371 237.707,229.371 238.126,228.951 238.126,227.587 238.493,227.22 244.385,227.22 245.46,226.145
  Top Layer w0.6: R52.2@222.997,179.526 222.997,178.202 223.54,177.659 224.751,177.659 C47.2@224.776,177.634 U10.3@224.776,176.234
  Top Layer w1: v2(203.968,29.757) 203.968,28.118 D3.2@204.086,28 ; T2.1@235.886,223.74 244.02,223.74 C61.1@245.5,225.22
  Bottom Layer w1: v2(203.968,29.757) 203.968,30.65 221.618,48.3 242.497,48.3 247.25,53.053 247.25,101.698 240.5,108.448 240.5,111.866 248.575,119.941 248.575,177.634 ; C9.1@231.591,177.82 248.389,177.82 248.575,177.634 ; v2(248.558,223.036) 248.575,223.019 248.575,177.634
15V_GateA: C126.2 C127.1 R61.1 U23.5 | length 272.7
  Top Layer w0.5: v2(123.445,199.336) 123.445,187.305 124.878,185.872 128.3,185.872 131.8,182.372 131.8,121.793 132.093,121.5 174.5,121.5 180.4,115.6 227.11,115.6 241.75,130.24 241.75,181.45 235.104,188.097 R61.1@232.45,188.097
  Bottom Layer w0.5: v2(123.031,207) 123.031,199.777 123.445,199.363 v2(123.445,199.336)
15V_GateB: C137.2 C138.1 R67.1 U25.5
15V_GateC: C134.2 C135.1 R64.1 U24.5 | length 350.3
  Top Layer w0.5: v2(49.797,198.548) 50.714,197.631 50.714,185.315 53.435,182.594 62.656,182.594 64.345,180.905 64.345,126.455 72.55,118.25 171.75,118.25 177.673,112.327 229.577,112.327 245.2,127.95 245.2,185.992 242.244,188.948 240.243,188.948 239.95,189.241 239.95,189.716 239.725,189.941 R64.1@239.7,189.941
  Bottom Layer w0.5: v2(49.532,206.169) 49.532,206.142 50.243,205.431 50.243,198.998 49.797,198.551 v2(49.797,198.548)
#GD_ENABLE: R137.2 R142.2 R143.2 U27.43 | length 393.8
  Top Layer w0.2: R137.2@131.213,205.044 131.233,205.023 v2(132.109,205.023) ; v2(188.259,139.25) 188.259,147.095 v2@188.059,147.295 ; v2(188.259,147.295) v2@188.059,147.295 ; v2(203.425,163.73) 203.425,161.402 202.561,160.538 191.291,160.538 188.059,157.306 v2@188.059,147.295
  Top Layer w0.3: R142.2@59.529,202.293 60.605,202.293 60.881,202.016 60.881,195.078 60.643,194.839 60.643,194.307 v2(60.586,194.25) ; v2(203.425,163.73) 199.646,167.509 199.646,182.49 205.615,188.459 205.615,195.674 206.368,196.426 R143.2@206.368,203.465 ; v2(209.414,161.977) 209.414,159.503 209.588,159.329 U27.43@209.588,156.377
  Bottom Layer w0.2: v2(60.586,194.25) 60.586,194.216 60.302,193.933 60.302,142.448 63.25,139.5 187.901,139.5 188.151,139.25 v2(188.259,139.25) ; v2(132.109,205.023) 132.109,205.011 132.414,204.706 132.414,188.136 141.366,179.184 141.366,147.808 141.832,147.342 188.213,147.342 v2(188.259,147.295)
  Bottom Layer w0.3: v2(203.425,163.73) 207.66,163.73 v2(209.414,161.977)
A3.3V: C154.1 L10.2 U27.18 | length 11
  Top Layer w0.3: L10.2@209.163,138.04 209.163,138.065 207.994,139.234 207.994,141.023 208.963,141.993 C154.1@208.963,142.018 208.963,143.889 209.588,144.514 U27.18@209.588,147.877
BROWNOUT: C44.1 R35.1 R50.2 U7.3 | length 11.1
  Top Layer w0.5: R35.1@202.016,265.839 202.016,266.004 202.401,266.389 202.566,266.389 203.457,267.28 207.154,267.28 207.546,266.888 R50.2@207.546,265.692 ; C44.1@207.546,264.062 209.386,264.062 209.436,264.012 U7.3@209.436,264
  Top Layer w0.8: R50.2@207.544,265.692 207.545,265.691 207.545,264.063 C44.1@207.546,264.062
DAC0: R144.1 U27.33 | length 4.8
  Top Layer w0.3: U27.33@214.088,153.377 216.667,153.377 217.042,153.752 R144.1@218.741,153.752
DAC1: R145.1 U27.34 | length 5.3
  Top Layer w0.3: U27.34@214.088,153.877 216.29,153.877 217.815,155.402 R145.1@218.805,155.402
EGND: C7.2 C8.2 GD1.1 J7.1 | length 123.5
  Top Layer w1: J7.1@20.185,1.815 20.78,1.815 21.595,1 C8.2@27.5,1 42.554,1 GD1.1@49.054,7.5
  Bottom Layer w1: GD1.1@49.054,7.5 54.854,1.7 122.8,1.7 123.75,0.75 134,0.75 134.75,1.5 C7.2@137.5,1.5
GND_ACSensing: C74.2 C75.2 C76.1 C77.1 C78.2 C79.1 C87.2 C88.1 C97.2 C98.1 R83.1 R86.2 R96.2 R99.2 R107.2 R110.2 T2.4 U14.1 U15.4 U17.4 U19.4 | length 244.7
  Top Layer w0.5: v2(213.29,34.584) C74.2@214.348,34.584 ; v2(214.028,32.892) C77.1@214.947,32.892 ; v2(214.25,9.509) 214.289,9.469 C97.2@215.787,9.469 ; v2(214.307,2.867) 214.307,2.9 214.328,2.921 R110.2@215.652,2.921 215.557,3.016 215.557,4.576 R107.2@215.462,4.671 ; v2(214.472,12.096) R86.2@215.763,12.096 ; v2(214.527,18.923) C78.2@215.475,18.923 ; v2(214.658,21.5) R99.2@215.85,21.5 215.775,21.576 215.775,23.186 R96.2@215.699,23.262 ; v2(214.751,7.754) C98.1@215.89,7.754 ; v2(214.775,17.251) C79.1@215.725,17.251 ; v2(214.808,28.26) 214.811,28.262 215.869,28.262 C87.2@215.872,28.265 ; v2(215.148,26.603) C88.1@216.061,26.603 ; R83.1@215.763,14.046 215.763,12.137 R86.2@215.783,12.116 ; v2(218.195,30.142) 218.279,30.226 U14.1@218.279,31.928 ; U19.4@219.677,3.565 219.677,2.524 219.714,2.486 219.714,2.463 v2(219.703,2.452) ; v2(219.677,12.371) U15.4@219.677,13.441 ; v2(219.677,21.225) U17.4@219.677,22.192 ; v2(224.947,35.635) 224.966,35.616 224.966,34.832 C76.1@225,34.798 ; v2(226.4,38.383) 243.008,38.383 247.669,43.044 247.669,99.231 239.2,107.7 239.2,114.1 248.4,123.3 248.4,205.245 241.539,212.106 240.943,212.106 C75.2@240.8,212.25
  Bottom Layer w1: T2.4@228.266,223.74 228.266,218.673 229.562,217.378 240.092,217.378 240.202,217.488
GND_GATEA: C59.1 C60.2 C126.1 C127.2 D17.2 Q2.3 Q3.3 R62.1 R159.2 T2.11 U23.8 | length 263.6
  Top Layer w0.5: v2(117.675,207) C127.2@118.784,207 ; v2(118.359,205.093) C126.1@119.329,205.093 ; Q2.3@119.648,184.55 128.436,184.55 131,181.986 131,121.043 131.293,120.75 174.096,120.75 180.019,114.827 227.327,114.827 242.45,129.95 242.45,181.74 234.554,189.637 v2(233.174,189.637) C59.1@232.366,189.637 ; U23.8@122.101,200.407 U23.8@122.501,200.407 ; D17.2@227.801,191.5 v2(228.611,191.5)
  Top Layer w1: v2(228.363,194.748) 228.4,194.711 R62.1@228.4,193.221
  Bottom Layer w0.5: v2(233.174,189.637) v2@233.179,189.637
  other v1: 119.698,182.95 118.298,183.65 121.098,183.65 118.098,185.25 121.198,185.25 119.698,186.15
  other v2: 121.782,196.543 121.5,197.294 122.496,197.294 121.5,198.197 122.408,198.209 122.408,198.964 121.94,199.619
GND_GATEB: C68.1 C70.2 C137.1 C138.2 D23.2 Q4.3 Q5.3 R70.1 R161.2 T2.7 U25.8 | length 4.7
  Top Layer w0.5: C138.2@190.987,207.807 v2(192.104,207.807) ; v2(191.448,205.816) C137.1@192.279,205.816 ; C68.1@200.164,207.807 200.164,207.832 200.551,208.22 v2(200.551,208.557) 200.57,208.577 200.57,208.924 201.127,209.481 R70.1@201.152,209.481 ; v2(208.795,220.45) D23.2@209.497,220.45
  other v1: 192.698,182.95 191.298,183.65 194.098,183.65 191.098,185.25 194.198,185.25 192.698,186.15
  other v2: 194.862,195.165 195.691,195.2 194.387,197.679 195.422,198.117 195.422,199.79 194.387,200.057
GND_GATEC: C64.1 C66.2 C134.1 C135.2 D21.2 Q6.3 Q7.3 R66.1 R160.2 T2.13 U24.8 | length 336.6
  Top Layer w0.5: C135.2@45.125,206.169 v2(46.243,206.169) ; v2(45.35,204.212) 45.37,204.232 46.108,204.232 C134.1@46.15,204.274 ; Q6.3@46.648,184.55 50.128,184.55 53,181.678 62.174,181.678 63.645,180.207 63.645,125.83 71.975,117.5 171.4,117.5 177.273,111.627 230.271,111.627 245.9,127.256 245.9,186.418 v2(242.646,189.672) ; v2(48.713,198.756) v2@48.713,198.783 ; U24.8@48.8,199.538 48.85,199.588 U24.8@49.25,199.588 ; v2(237.371,191.5) C64.1@237.371,192.3 ; v2(239.024,191.017) R66.1@239.024,192.05 ; v2(240.7,192.275) 240.7,191.55 D21.2@240.75,191.5
  other v1: 46.698,182.95 45.298,183.65 48.098,183.65 45.098,185.25 48.198,185.25 46.698,186.15
  other v2: 49.065,194.91 49.061,195.838 49.022,196.749 49.436,197.631
GND_ISO: C142.2 J9.4 U26.5 | length 2.3
  Top Layer w0.6: C142.2@205.458,175.359 205.495,175.322 v2(206.489,175.322) ; U26.5@210.937,173.637 v2(210.937,174.939)
HS_TEMP_AD: C145.2 J12.2 R150.1 RT2.2 U27.19 | length 19.5
  Top Layer w0.3: RT2.2@208.463,132.22 208.463,133.212 208.834,133.583 J12.2@210.477,133.583 211.894,135 211.894,136.9 210.779,138.015 R150.1@210.779,138.04 210.779,138.065 211.588,138.874 211.588,140.918 210.613,141.893 C145.2@210.588,141.893 210.588,143.487 210.088,143.987 U27.19@210.088,147.877
IA_AD: C12.1 R13.1 U27.15 | length 11.2
  Top Layer w0.3: R13.1@206.578,138.04 206.903,138.365 206.903,139.197 207.463,139.756 207.463,141.09 206.563,141.99 C12.1@206.563,142.015 206.563,142.04 208.088,143.565 U27.15@208.088,147.877
IB_AD: C17.1 R15.1 U27.21 | length 12.2
  Top Layer w0.3: U27.21@211.088,147.877 211.088,145.869 214.904,142.053 C17.1@214.904,142.028 214.904,142.003 215.878,141.029 215.878,138.98 214.963,138.065 R15.1@214.963,138.04
IC_AD: C21.1 R18.1 U27.8 | length 9.7
  Top Layer w0.3: R18.1@196.668,151.252 196.693,151.252 197.518,150.427 199.864,150.427 200.689,151.252 C21.1@200.714,151.252 202.988,151.252 203.113,151.377 U27.8@205.588,151.377
LED1C_C2K: D25.2 U27.27 | length 7.2
  Top Layer w0.3: U27.27@214.088,150.377 215.671,150.377 216.667,149.38 216.667,148.32 218.359,146.628 D25.2@219.158,146.628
